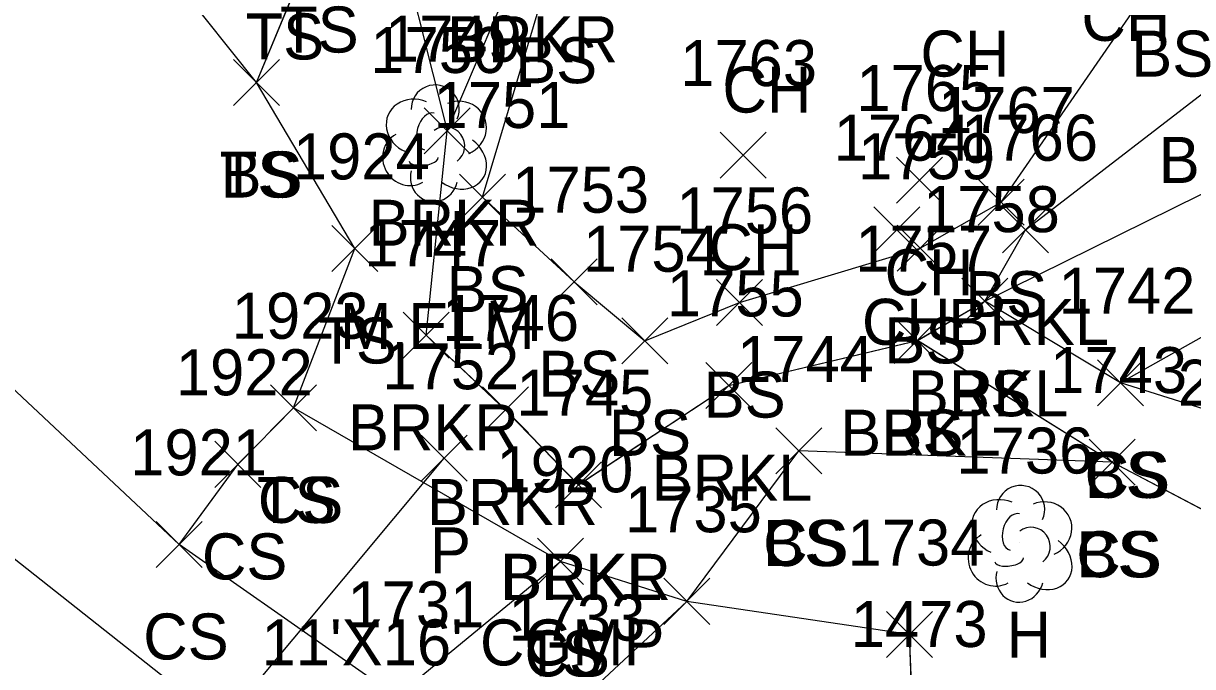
# Model space of a CAD drawing. Extents: x 1415642 to 1422021, y 544543 to 547232.
# Drawn here: x 1416156.1 to 1416207, y 546840.3 to 546868.3 of the extents above; entities that cross this region are included whole.
import ezdxf

# ---------------------------------------------------------------- set-up
doc = ezdxf.new("R2010")
doc.units = 0
for name, color, linetype in [('D_A', 7, 'Continuous'), ('D_C', 7, 'Continuous'), ('D_I', 7, 'Continuous'), ('D_TIC', 7, 'Continuous'), ('DCP', 7, 'Continuous'), ('L_A', 7, 'Continuous'), ('L_C', 7, 'Continuous'), ('L_I', 7, 'Continuous'), ('L_TIC', 7, 'Continuous'), ('LAWE', 7, 'Continuous'), ('LELB', 7, 'Continuous'), ('LTD', 7, 'Continuous'), ('RGR', 7, 'Continuous')]:
    doc.layers.add(name, color=color, linetype=linetype)

msp = doc.modelspace()

# ---------------------------------------------------------------- linework, layer by layer
at = {"layer": 'D_TIC'}
for points in [[(1416173.435, 546848.379), (1416175.435, 546850.379)], [(1416175.435, 546848.379), (1416173.435, 546850.379)]]:
    msp.add_lwpolyline(points, dxfattribs=at)
at = {"layer": 'DCP'}
for points in [[(1416130.863, 546797.224), (1416174.435, 546849.379)], [(1416130.871, 546797.224), (1416174.434, 546849.38)]]:
    msp.add_lwpolyline(points, dxfattribs=at)
at = {"layer": 'L_TIC'}
for points in [[(1416165.265, 546864.71), (1416167.265, 546866.71)], [(1416167.265, 546864.71), (1416165.265, 546866.71)], [(1416165.265, 546864.71), (1416167.265, 546866.71)], [(1416167.265, 546864.71), (1416165.265, 546866.71)], [(1416173.556, 546862.614), (1416175.556, 546864.614)], [(1416175.556, 546862.614), (1416173.556, 546864.614)], [(1416186.432, 546861.551), (1416188.432, 546863.551)], [(1416188.432, 546861.551), (1416186.432, 546863.551)], [(1416194.091, 546860.465), (1416196.091, 546862.465)], [(1416196.091, 546860.465), (1416194.091, 546862.465)], [(1416175.093, 546859.732), (1416177.093, 546861.732)], [(1416177.093, 546859.732), (1416175.093, 546861.732)], [(1416175.093, 546859.732), (1416177.093, 546861.732)], [(1416177.093, 546859.732), (1416175.093, 546861.732)], [(1416197.642, 546859.512), (1416199.642, 546861.512)], [(1416199.642, 546859.512), (1416197.642, 546861.512)], [(1416193.106, 546858.31), (1416195.106, 546860.31)], [(1416195.106, 546858.31), (1416193.106, 546860.31)], [(1416198.703, 546858.308), (1416200.703, 546860.308)], [(1416200.703, 546858.308), (1416198.703, 546860.308)], [(1416169.548, 546857.498), (1416171.548, 546859.498)], [(1416171.548, 546857.498), (1416169.548, 546859.498)], [(1416194.126, 546857.505), (1416196.126, 546859.505)], [(1416196.126, 546857.505), (1416194.126, 546859.505)], [(1416179.082, 546856.051), (1416181.082, 546858.051)], [(1416181.082, 546856.051), (1416179.082, 546858.051)], [(1416186.271, 546855.147), (1416188.271, 546857.147)], [(1416188.271, 546855.147), (1416186.271, 546857.147)], [(1416196.943, 546855.205), (1416198.943, 546857.205)], [(1416198.943, 546855.205), (1416196.943, 546857.205)], [(1416196.943, 546855.205), (1416198.943, 546857.205)], [(1416198.943, 546855.205), (1416196.943, 546857.205)], [(1416172.654, 546853.727), (1416174.654, 546855.727)], [(1416174.654, 546853.727), (1416172.654, 546855.727)], [(1416182.156, 546853.486), (1416184.156, 546855.486)], [(1416184.156, 546853.486), (1416182.156, 546855.486)], [(1416194, 546853.494), (1416196, 546855.494)], [(1416196, 546853.494), (1416194, 546855.494)], [(1416194, 546853.494), (1416196, 546855.494)], [(1416196, 546853.494), (1416194, 546855.494)], [(1416185.806, 546851.542), (1416187.806, 546853.542)], [(1416187.806, 546851.542), (1416185.806, 546853.542)], [(1416202.833, 546851.66), (1416204.833, 546853.66)], [(1416204.833, 546851.66), (1416202.833, 546853.66)], [(1416202.833, 546851.66), (1416204.833, 546853.66)], [(1416204.833, 546851.66), (1416202.833, 546853.66)], [(1416166.887, 546850.572), (1416168.887, 546852.572)], [(1416168.887, 546850.572), (1416166.887, 546852.572)], [(1416166.887, 546850.572), (1416168.887, 546852.572)], [(1416168.887, 546850.572), (1416166.887, 546852.572)], [(1416176.092, 546850.48), (1416178.092, 546852.48)], [(1416178.092, 546850.48), (1416176.092, 546852.48)], [(1416188.856, 546848.7), (1416190.856, 546850.7)], [(1416190.856, 546848.7), (1416188.856, 546850.7)], [(1416188.856, 546848.7), (1416190.856, 546850.7)], [(1416190.856, 546848.7), (1416188.856, 546850.7)], [(1416164.458, 546848.117), (1416166.458, 546850.117)], [(1416166.458, 546848.117), (1416164.458, 546850.117)], [(1416202.474, 546848.211), (1416204.474, 546850.211)], [(1416204.474, 546848.211), (1416202.474, 546850.211)], [(1416202.474, 546848.211), (1416204.474, 546850.211)], [(1416204.474, 546848.211), (1416202.474, 546850.211)], [(1416179.264, 546847.229), (1416181.264, 546849.229)], [(1416181.264, 546847.229), (1416179.264, 546849.229)], [(1416179.264, 546847.229), (1416181.264, 546849.229)], [(1416181.264, 546847.229), (1416179.264, 546849.229)], [(1416161.906, 546844.637), (1416163.906, 546846.637)], [(1416163.906, 546844.637), (1416161.906, 546846.637)], [(1416161.906, 546844.637), (1416163.906, 546846.637)], [(1416163.906, 546844.637), (1416161.906, 546846.637)], [(1416178.483, 546843.903), (1416180.483, 546845.903)], [(1416180.483, 546843.903), (1416178.483, 546845.903)], [(1416178.483, 546843.903), (1416180.483, 546845.903)], [(1416180.483, 546843.903), (1416178.483, 546845.903)], [(1416183.984, 546842.165), (1416185.984, 546844.165)], [(1416185.984, 546842.165), (1416183.984, 546844.165)], [(1416183.984, 546842.165), (1416185.984, 546844.165)], [(1416185.984, 546842.165), (1416183.984, 546844.165)], [(1416193.662, 546840.719), (1416195.662, 546842.719)], [(1416195.662, 546840.719), (1416193.662, 546842.719)]]:
    msp.add_lwpolyline(points, dxfattribs=at)
at = {"layer": 'LAWE'}
for points in [[(1416180.264, 546848.229), (1416177.092, 546851.48), (1416173.654, 546854.727), (1416174.556, 546863.614), (1416177.966, 546871.587), (1416177.372, 546877.166)], [(1416180.263, 546848.23), (1416177.089, 546851.481), (1416173.655, 546854.727), (1416174.555, 546863.614), (1416177.972, 546871.586), (1416177.378, 546877.165)], [(1416180.263, 546848.23), (1416186.81, 546852.541), (1416195.004, 546854.493), (1416197.941, 546856.205), (1416199.704, 546859.308), (1416208.851, 546866.343)], [(1416180.264, 546848.229), (1416186.806, 546852.542), (1416195, 546854.494), (1416197.943, 546856.205), (1416199.703, 546859.308), (1416208.852, 546866.343)]]:
    msp.add_lwpolyline(points, dxfattribs=at)
at = {"layer": 'LELB'}
for points in [[(1416166.265, 546865.71), (1416159.514, 546874.184), (1416128.857, 546893.051), (1416099.942, 546911.946), (1416080.109, 546927.167), (1416051.607, 546951.273), (1416024.788, 546978.542), (1415989.847, 547005.498), (1415949.916, 547022.61), (1415918.775, 547047.798), (1415880.242, 547071.016), (1415848.802, 547092.398)], [(1416166.265, 546865.71), (1416159.513, 546874.184), (1416128.861, 546893.052), (1416099.946, 546911.942), (1416080.11, 546927.168), (1416051.609, 546951.273), (1416024.792, 546978.539), (1415989.849, 547005.496), (1415949.921, 547022.607), (1415918.779, 547047.795), (1415880.245, 547071.014), (1415848.804, 547092.397)], [(1416210.449, 546810.143), (1416187.238, 546828.497), (1416172.356, 546839.03), (1416162.908, 546845.636), (1416145.696, 546861.763), (1416125.163, 546875.536), (1416093.403, 546901.435), (1416075.184, 546919.901), (1416045.659, 546942.323), (1416039.773, 546946.289), (1416015.879, 546971.975), (1415979.907, 546993.699), (1415946.506, 547018.197), (1415914.221, 547042.269), (1415877.244, 547066.677), (1415845.5, 547087.741)], [(1416210.45, 546810.142), (1416187.236, 546828.498), (1416172.351, 546839.033), (1416162.906, 546845.637), (1416145.693, 546861.764), (1416125.164, 546875.535), (1416093.403, 546901.434), (1416075.185, 546919.898), (1416045.659, 546942.323), (1416039.768, 546946.292), (1416015.881, 546971.972), (1415979.908, 546993.697), (1415946.504, 547018.199), (1415914.218, 547042.271), (1415877.246, 547066.675), (1415845.502, 547087.738)], [(1416176.093, 546860.732), (1416180.087, 546857.049), (1416183.159, 546854.485), (1416187.271, 546856.147), (1416195.123, 546858.506), (1416198.641, 546860.512), (1416205.866, 546870.961), (1416221.045, 546890.959)], [(1416176.093, 546860.732), (1416180.082, 546857.051), (1416183.156, 546854.486), (1416187.271, 546856.147), (1416195.126, 546858.505), (1416198.642, 546860.512), (1416205.86, 546870.962), (1416221.039, 546890.958)], [(1416176.093, 546860.732), (1416179.075, 546870.677), (1416187.519, 546880.949)], [(1416176.093, 546860.732), (1416179.074, 546870.677), (1416187.522, 546880.948)], [(1416225.048, 546830.585), (1416212.797, 546833.843), (1416194.801, 546838.18), (1416194.662, 546841.719), (1416184.984, 546843.165), (1416179.483, 546844.903), (1416167.887, 546851.572), (1416170.548, 546858.498), (1416166.265, 546865.71), (1416168.887, 546872.01), (1416167.385, 546871.708), (1416162.57, 546875.357), (1416165.046, 546879.987), (1416171.514, 546876.268)], [(1416225.049, 546830.584), (1416212.797, 546833.845), (1416194.799, 546838.183), (1416194.662, 546841.718), (1416184.984, 546843.165), (1416179.486, 546844.901), (1416167.885, 546851.573), (1416170.55, 546858.497), (1416166.265, 546865.71), (1416168.891, 546872.009), (1416167.387, 546871.708), (1416162.572, 546875.356), (1416165.05, 546879.986), (1416171.516, 546876.267)], [(1416172.052, 546873.591), (1416174.556, 546863.614)], [(1416172.057, 546873.591), (1416174.555, 546863.614)], [(1416399.906, 546654.534), (1416394.347, 546666.375), (1416375.333, 546699.787), (1416357.077, 546731.493), (1416339.454, 546773.581), (1416310.343, 546806.722), (1416282.706, 546825.534), (1416242.807, 546844.041), (1416212.625, 546849.893), (1416203.831, 546852.661), (1416197.941, 546856.205), (1416209.641, 546861.986)], [(1416399.907, 546654.532), (1416394.345, 546666.378), (1416375.33, 546699.79), (1416357.074, 546731.494), (1416339.456, 546773.581), (1416310.342, 546806.721), (1416282.704, 546825.53), (1416242.805, 546844.045), (1416212.627, 546849.893), (1416203.833, 546852.66), (1416197.943, 546856.205), (1416209.643, 546861.986)], [(1416210.611, 546856.474), (1416203.831, 546852.661)], [(1416210.611, 546856.474), (1416203.833, 546852.66)], [(1416487.567, 546505.93), (1416480.706, 546505.117), (1416469.863, 546502.717), (1416462.762, 546510.547), (1416442.834, 546541.19), (1416430.44, 546560.715), (1416424.351, 546585.185), (1416398.34, 546624.279), (1416389.664, 546643.264), (1416377.296, 546653.034), (1416344.541, 546704.054), (1416343.421, 546724.766), (1416329.349, 546768.045), (1416303.679, 546799.518), (1416274.803, 546819.392), (1416239.261, 546839.408), (1416210.605, 546845.462), (1416203.474, 546849.211), (1416195, 546854.494)], [(1416487.569, 546505.931), (1416480.706, 546505.118), (1416469.858, 546502.715), (1416462.759, 546510.548), (1416442.834, 546541.191), (1416430.438, 546560.718), (1416424.353, 546585.182), (1416398.34, 546624.281), (1416389.663, 546643.265), (1416377.298, 546653.032), (1416344.543, 546704.052), (1416343.424, 546724.765), (1416329.347, 546768.045), (1416303.677, 546799.515), (1416274.804, 546819.396), (1416239.262, 546839.409), (1416210.611, 546845.46), (1416203.478, 546849.209), (1416195.004, 546854.493)], [(1416162.906, 546845.637), (1416165.458, 546849.117), (1416167.887, 546851.572)], [(1416162.908, 546845.636), (1416165.458, 546849.117), (1416167.885, 546851.573)], [(1416307.151, 546711.363), (1416298.601, 546718.219), (1416262.672, 546753.939), (1416226.79, 546787.66), (1416210.45, 546810.142), (1416201.524, 546824.858), (1416194.801, 546838.18), (1416185.88, 546835.278), (1416179.92, 546838.455), (1416184.984, 546843.165), (1416189.856, 546849.7)], [(1416307.151, 546711.363), (1416298.6, 546718.221), (1416262.673, 546753.94), (1416226.789, 546787.661), (1416210.449, 546810.143), (1416201.526, 546824.856), (1416194.799, 546838.183), (1416185.88, 546835.279), (1416179.923, 546838.454), (1416184.984, 546843.165), (1416189.857, 546849.7)], [(1416203.474, 546849.211), (1416189.856, 546849.7)], [(1416203.478, 546849.209), (1416189.857, 546849.7)], [(1416172.351, 546839.033), (1416179.483, 546844.903)], [(1416172.356, 546839.03), (1416179.486, 546844.901)]]:
    msp.add_lwpolyline(points, dxfattribs=at)
at = {"layer": 'LTD'}
for p, q in [((1416173.996, 546863.122), (1416173.996, 546863.122)), ((1416173.996, 546863.122), (1416173.996, 546863.122)), ((1416199.452, 546845.717), (1416199.452, 546845.717)), ((1416199.452, 546845.717), (1416199.452, 546845.717))]:
    msp.add_line(p, q, dxfattribs=at)
for centre in [(1416174.043, 546864.556), (1416199.498, 546847.151)]:
    msp.add_arc(centre, 1.047, 335.5272, 180.9563, dxfattribs=at)
for centre, major_axis, ratio, start_param, end_param in [((1416173.204, 546863.788), (1.21, -0.512), 0.895232, 1.570796, 4.712389), ((1416175.038, 546863.705), (-1.141, -0.483), 0.949671, 1.570796, 4.712389), ((1416173.788, 546863.58), (-0.208, -0.792), 0.645439, 3.141593, 6.283185), ((1416174.496, 546862.955), (-0.5, 0.667), 0.989748, 3.141593, 6.283185), ((1416172.913, 546862.413), (0.584, -1.042), 0.959034, 3.141593, 6.283185), ((1416174.996, 546862.289), (-1.09, 0.792), 0.841452, 1.570796, 4.712389), ((1416173.538, 546862.372), (-0.625, -0.083), 0.423636, 0, 3.141593), ((1416173.997, 546861.622), (0.265, 1.061), 0.942809, 1.570796, 4.712389), ((1416198.66, 546846.384), (1.21, -0.512), 0.895232, 1.570796, 4.712389), ((1416200.493, 546846.301), (-1.141, -0.483), 0.949671, 1.570796, 4.712389), ((1416199.243, 546846.175), (-0.208, -0.792), 0.645439, 3.141593, 6.283185), ((1416199.952, 546845.551), (-0.5, 0.667), 0.989748, 3.141593, 6.283185), ((1416198.368, 546845.009), (0.584, -1.042), 0.959034, 3.141593, 6.283185), ((1416200.452, 546844.884), (-1.09, 0.792), 0.841452, 1.570796, 4.712389), ((1416198.993, 546844.967), (-0.625, -0.083), 0.423636, 0, 3.141593), ((1416199.452, 546844.217), (0.265, 1.061), 0.942809, 1.570796, 4.712389)]:
    msp.add_ellipse(centre, major_axis=major_axis, ratio=ratio, start_param=start_param, end_param=end_param, dxfattribs=at)
at = {"layer": 'RGR'}
for points in [[(1416226.79, 546787.66), (1416201.13, 546806.067), (1416168.801, 546834.687), (1416149.29, 546850.099), (1416119.316, 546873.14), (1416091.473, 546896.231), (1416072.683, 546914.463)], [(1416226.789, 546787.661), (1416201.129, 546806.068), (1416168.806, 546834.683), (1416149.293, 546850.097), (1416119.319, 546873.137), (1416091.474, 546896.23), (1416072.684, 546914.463)]]:
    msp.add_lwpolyline(points, dxfattribs=at)

# ---------------------------------------------------------------- texts
at = {"layer": 'D_A'}
msp.add_text('P', height=2, dxfattribs=at).set_placement((1416173.813, 546844.379))
at = {"layer": 'D_C'}
msp.add_text("11'X16' CGMP", height=2, dxfattribs=at).set_placement((1416166.49, 546840.379))
at = {"layer": 'D_I'}
msp.add_text('1752', height=2, dxfattribs=at).set_placement((1416171.742, 546852.379))
at = {"layer": 'L_A'}
for s, p in [('CH', (1416202.134, 546867.516)), ('TS', (1416165.795, 546866.708)), ('TS', (1416167.297, 546867.01)), ('BRKR', (1416174.557, 546866.587)), ('BS', (1416177.516, 546865.677)), ('CH', (1416195.136, 546865.964)), ('BS', (1416204.301, 546865.962)), ('CH', (1416186.536, 546864.4)), ('BRKL', (1416205.498, 546861.343)), ('TS', (1416164.674, 546860.71)), ('BS', (1416164.706, 546860.71)), ('BRKR', (1416171.146, 546858.614)), ('H', (1416173.429, 546858.122)), ('CH', (1416185.92, 546857.551)), ('CH', (1416193.58, 546856.465)), ('BS', (1416174.534, 546855.732)), ('BS', (1416174.534, 546855.732)), ('BS', (1416197.083, 546855.512)), ('CH', (1416192.594, 546854.31)), ('BRKL', (1416196.349, 546854.308)), ('TS', (1416168.957, 546853.498)), ('BS', (1416193.567, 546853.505)), ('BS', (1416178.522, 546852.051)), ('BS', (1416185.712, 546851.147)), ('BRKL', (1416194.589, 546851.205)), ('BS', (1416196.384, 546851.205)), ('BRKR', (1416170.245, 546849.727)), ('BS', (1416181.597, 546849.486)), ('BRKL', (1416191.646, 546849.494)), ('BS', (1416193.441, 546849.494)), ('BRKL', (1416183.452, 546847.542)), ('CS', (1416202.274, 546847.66)), ('BS', (1416202.274, 546847.66)), ('TS', (1416166.297, 546846.572)), ('CS', (1416166.328, 546846.572)), ('BRKR', (1416173.682, 546846.48)), ('CS', (1416188.297, 546844.7)), ('BS', (1416188.297, 546844.7)), ('CS', (1416201.915, 546844.211)), ('BS', (1416201.915, 546844.211)), ('CS', (1416163.899, 546844.117)), ('BRKR', (1416176.855, 546843.229)), ('BRKL', (1416176.91, 546843.229)), ('H', (1416198.885, 546840.717)), ('CS', (1416161.347, 546840.637)), ('CS', (1416161.347, 546840.637)), ('TS', (1416177.892, 546839.903)), ('CS', (1416177.924, 546839.903))]:
    msp.add_text(s, height=2, dxfattribs=at).set_placement(p)
at = {"layer": 'L_C'}
for s, p in [('M.ELM', (1416169.902, 546854.122)), ('2-M. ELM', (1416206.324, 546851.664))]:
    msp.add_text(s, height=2, dxfattribs=at).set_placement(p)
at = {"layer": 'L_I'}
for s, p in [('1749', (1416171.855, 546866.614)), ('1750', (1416171.217, 546866.122)), ('1763', (1416184.692, 546865.551)), ('1765', (1416192.351, 546864.465)), ('1751', (1416173.968, 546863.732)), ('1751', (1416173.968, 546863.732)), ('1767', (1416195.902, 546863.512)), ('1764', (1416191.366, 546862.31)), ('1766', (1416196.908, 546862.308)), ('1924', (1416167.855, 546861.498)), ('1759', (1416192.425, 546861.505)), ('1753', (1416177.389, 546860.051)), ('1756', (1416184.523, 546859.147)), ('1758', (1416195.25, 546859.205)), ('1758', (1416195.25, 546859.205)), ('1747', (1416170.962, 546857.727)), ('1754', (1416180.463, 546857.486)), ('1757', (1416192.307, 546857.494)), ('1757', (1416192.307, 546857.494)), ('1755', (1416184.113, 546855.542)), ('1742', (1416201.14, 546855.66)), ('1742', (1416201.14, 546855.66)), ('1923', (1416165.195, 546854.572)), ('1923', (1416165.195, 546854.572)), ('1746', (1416174.344, 546854.48)), ('1744', (1416187.163, 546852.7)), ('1744', (1416187.163, 546852.7)), ('1922', (1416162.765, 546852.117)), ('1743', (1416200.781, 546852.211)), ('1743', (1416200.781, 546852.211)), ('1745', (1416177.571, 546851.229)), ('1745', (1416177.571, 546851.229)), ('1921', (1416160.78, 546848.637)), ('1921', (1416160.78, 546848.637)), ('1736', (1416196.704, 546848.717)), ('1920', (1416176.703, 546847.903)), ('1920', (1416176.703, 546847.903)), ('1735', (1416182.291, 546846.165)), ('1735', (1416182.291, 546846.165)), ('1734', (1416191.969, 546844.719)), ('1731', (1416170.225, 546842.033)), ('1731', (1416170.225, 546842.033)), ('1733', (1416177.227, 546841.455)), ('1473', (1416192.108, 546841.18)), ('1473', (1416192.108, 546841.18))]:
    msp.add_text(s, height=2, dxfattribs=at).set_placement(p)

doc.saveas('drawing.dxf')
